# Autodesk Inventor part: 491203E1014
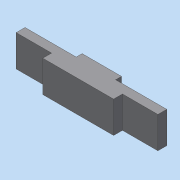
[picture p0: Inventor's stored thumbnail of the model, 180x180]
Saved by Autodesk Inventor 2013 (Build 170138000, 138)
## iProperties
Created: 2019-12
Part Number: 491203E1014
Material: 일반
Document SubType Name: Modeling
Designer: dgall
Density: 1 g/cm^3
Author: dgall
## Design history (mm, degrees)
sketch "스케치1"
  geometry: L1 (-36, 0)-(36, 0); L2 (-36, -3)-(-36, -7.5); L3 (-36, -7.5)-(-18, -7.5); L4 (-18, -7.5)-(-18, -12); L5 (-18, -12)-(18, -12); L6 (18, -12)-(18, -7.5); L7 (18, -7.5)-(36, -7.5); L8 (36, -7.5)-(36, -3); L9 (36, -3)-(10, -3); L10 (10, -3)-(10, 0); L11 (10, 0)-(-10, 0); L12 (-10, 0)-(-10, -3); L13 (-10, -3)-(-36, -3); 5 further points
  constraints: 26 end point, 6 parallel, 5 midpoint, 4 perpendicular, 2 coincident, 2 collinear, 2 equal length, 1 horizontal, 1 horizontal alignment, 1 vertical alignment
  dimensions: "d0" = 72 distance of L1.start L1.end; "d1" = 72 distance between parallel lines of L8 L2; "d2" = 12 distance between parallel lines of L5 L11; "d3" = 36 distance of L4.end L5.end; "d4" = 20 distance of L10.end L11.end; "d5" = 4.5 distance of L5.end L6.end; "d6" = 9 distance between parallel lines of L13 L5
extrude "돌출1" new body sketch "스케치1" distance "d7" = 16; taper "d8" = 0 deg
node "솔리드1"
